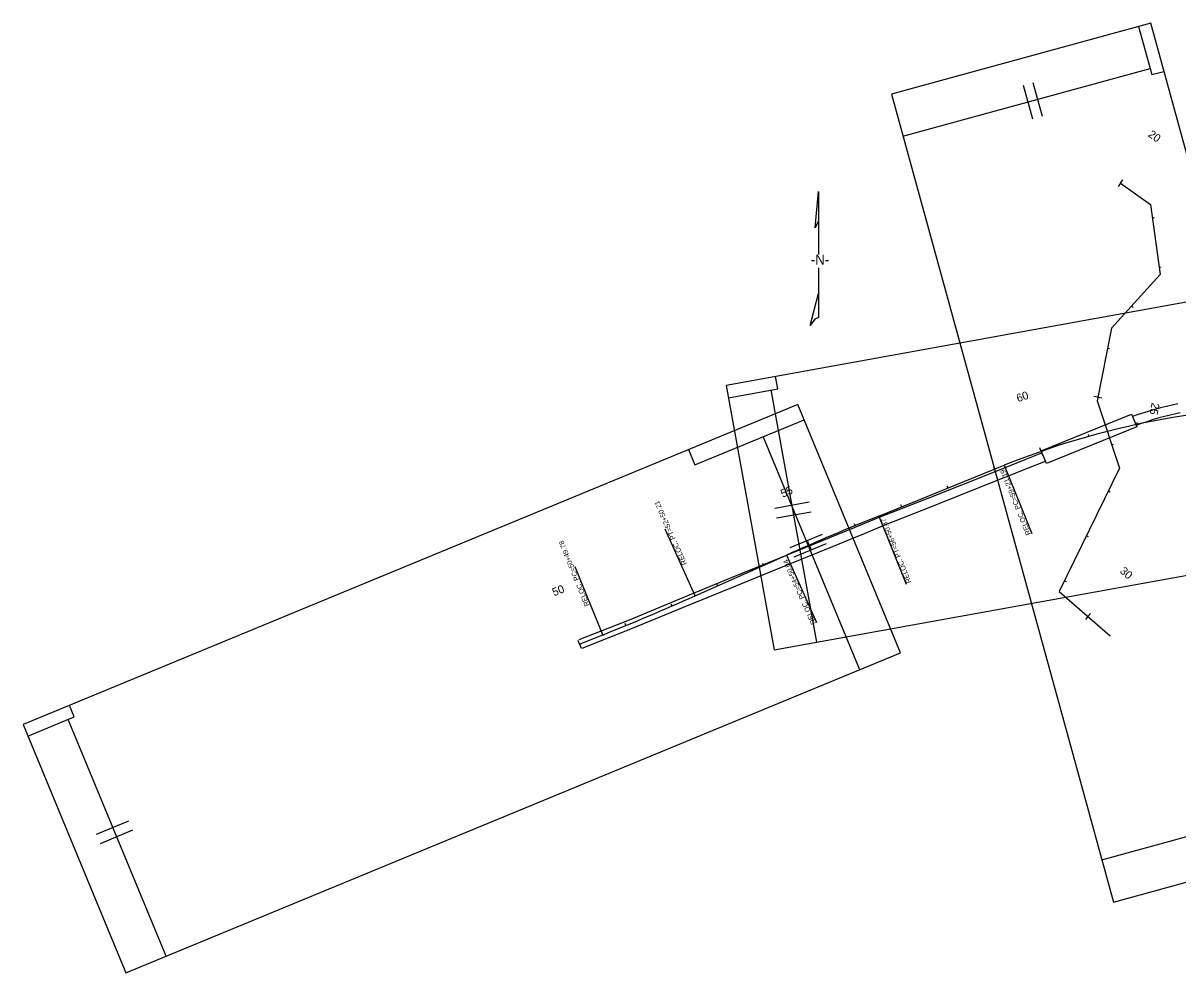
# Model space of a CAD drawing. Extents: x 1965658 to 1970277, y 1116791 to 1119319.
# Drawn here: x 1965658 to 1967966, y 1116791 to 1118690 of the extents above; entities that cross this region are included whole.
import ezdxf

# ---------------------------------------------------------------- set-up
doc = ezdxf.new("R2010")
doc.units = 0
for name, color, linetype in [('RD_EX_Bridge', 7, 'Continuous'), ('RD_EX_Misc', 7, 'Continuous'), ('RD_EX_Road', 7, 'Continuous'), ('RD_HC_CL', 7, 'Continuous'), ('RD_HC_CL_Rel', 7, 'Continuous'), ('RD_HC_Data_Rel', 7, 'Continuous'), ('RD_HC_Data_Tic', 7, 'Continuous'), ('RD_HC_Data_Tic_Rel', 7, 'Continuous'), ('RD_HC_TX_Rel_Sta50', 7, 'Continuous'), ('RD_HC_TX_Sta50', 7, 'Continuous'), ('RD_SHT_Bndy', 7, 'Continuous')]:
    doc.layers.add(name, color=color, linetype=linetype)

msp = doc.modelspace()

# ---------------------------------------------------------------- linework, layer by layer
at = {"layer": 'RD_EX_Bridge'}
msp.add_lwpolyline([(1967693.2, 1117834.7), (1967873.6, 1117908.4), (1967884, 1117883.1), (1967703.5, 1117809.4), (1967693.2, 1117834.7)], dxfattribs=at)
at = {"layer": 'RD_EX_Misc'}
for p, q in [((1967241.5, 1118281), (1967248.2, 1118353.8)), ((1967248.2, 1118353.8), (1967248.2, 1118294.5)), ((1967248.2, 1118294.5), (1967241.5, 1118281)), ((1967248.2, 1118294.5), (1967248.2, 1118253.4)), ((1967248.2, 1118253.4), (1967248.2, 1118227.2)), ((1967248.2, 1118201.1), (1967248.2, 1118149.3)), ((1967231.7, 1118085.8), (1967248.2, 1118149.3)), ((1967248.2, 1118149.3), (1967248.2, 1118141.4)), ((1967248.2, 1118141.4), (1967248.2, 1118101.8))]:
    msp.add_line(p, q, dxfattribs=at)
msp.add_lwpolyline([(1967248.2, 1118101.8), (1967241.1, 1118097.9), (1967231.7, 1118085.8)], dxfattribs=at)
at = {"layer": 'RD_EX_Road'}
msp.add_line((1967308.8, 1117656.7), (1967340, 1117669.9), dxfattribs=at)
for points in [[(1966769.5, 1117457.5), (1966870.2, 1117497.3), (1966971.2, 1117539), (1967071.1, 1117580.2), (1967172.6, 1117621.5), (1967270.8, 1117661.7), (1967321.1, 1117682.6), (1967371.5, 1117702.9), (1967470.3, 1117741.6), (1967566.7, 1117779.5), (1967661.2, 1117817.5), (1967694.6, 1117831.3)], [(1967340, 1117669.9), (1967379.3, 1117686.2), (1967476.1, 1117724.4), (1967573.9, 1117763.5), (1967667.7, 1117800.7), (1967701.6, 1117814)], [(1966775.8, 1117440.6), (1966876.2, 1117480.4), (1966978.5, 1117522.1), (1967078.3, 1117563.1), (1967180.7, 1117605.1), (1967278, 1117644.7), (1967308.8, 1117656.7)]]:
    msp.add_lwpolyline(points, dxfattribs=at)
for centre, radius, start, end in [((1968104.9, 1117261.1), 682.1, 101.7162, 109.6396), ((1968081.5, 1117359.5), 562.4, 101.3634, 110.7161)]:
    msp.add_arc(centre, radius, start, end, dxfattribs=at)
at = {"layer": 'RD_HC_CL'}
for p, q in [((1967851.7, 1118370.2), (1967911.4, 1118327.7)), ((1967911.4, 1118327.7), (1967931.1, 1118187.5)), ((1967931.1, 1118187.5), (1967834, 1118080)), ((1967834, 1118080), (1967804.8, 1117934.9)), ((1967804.8, 1117934.9), (1967849.8, 1117800.6)), ((1967849.8, 1117800.6), (1967729.3, 1117553.7)), ((1967729.3, 1117553.7), (1967830.8, 1117465.4))]:
    msp.add_line(p, q, dxfattribs=at)
at = {"layer": 'RD_HC_CL_Rel'}
for p, q in [((1967368.4, 1117704.6), (1967619.4, 1117806)), ((1967001.4, 1117545.1), (1967183.9, 1117626.3)), ((1966770.7, 1117448.1), (1966816.9, 1117466.8))]:
    msp.add_line(p, q, dxfattribs=at)
for centre, radius, start, end in [((1968232.6, 1116288.2), 1637, 87.7266, 111.9958), ((1969514.4, 1112392.1), 5729.6, 111.99584, 114.00015), ((1964670.9, 1122779.3), 5729.6, 291.9959, 294.00015)]:
    msp.add_arc(centre, radius, start, end, dxfattribs=at)
at = {"layer": 'RD_HC_Data_Rel'}
for p, q in [((1967619.4, 1117806), (1967674.6, 1117669.5)), ((1967368.4, 1117704.6), (1967423.4, 1117568.5)), ((1967001.4, 1117545.1), (1966941.9, 1117678.6)), ((1967183.9, 1117626.3), (1967243.9, 1117491.8)), ((1966816.9, 1117466.8), (1966761.8, 1117603.2))]:
    msp.add_line(p, q, dxfattribs=at)
at = {"layer": 'RD_HC_Data_Tic'}
for p, q in [((1967851.7, 1118370.2), (1967856.4, 1118376.7)), ((1967851.7, 1118370.2), (1967847.1, 1118363.7)), ((1967915.1, 1118301.2), (1967919, 1118301.7)), ((1967929, 1118202.2), (1967933, 1118202.7)), ((1967874, 1118124.2), (1967876.9, 1118121.6)), ((1967826.1, 1118040.4), (1967830, 1118039.6)), ((1967806.3, 1117942.4), (1967798.5, 1117943.9)), ((1967806.3, 1117942.4), (1967814.2, 1117940.8)), ((1967834.2, 1117847.3), (1967838, 1117848.6)), ((1967827.6, 1117755), (1967831.1, 1117753.2)), ((1967783.7, 1117665.1), (1967787.3, 1117663.4)), ((1967739.8, 1117575.2), (1967743.4, 1117573.5)), ((1967786.6, 1117503.8), (1967781.4, 1117497.8)), ((1967786.6, 1117503.8), (1967791.9, 1117509.8))]:
    msp.add_line(p, q, dxfattribs=at)
at = {"layer": 'RD_HC_Data_Tic_Rel'}
for p, q in [((1967885.6, 1117888), (1967884.7, 1117891.9)), ((1967788.6, 1117863.8), (1967787.5, 1117867.7)), ((1967693.2, 1117833.8), (1967690.6, 1117841.3)), ((1967693.2, 1117833.8), (1967695.8, 1117826.2)), ((1967599.8, 1117798.1), (1967598.3, 1117801.8)), ((1967507.1, 1117760.7), (1967505.6, 1117764.4)), ((1967414.4, 1117723.2), (1967412.9, 1117726.9)), ((1967321.7, 1117685.5), (1967320.2, 1117689.2)), ((1967229.7, 1117646.5), (1967226.5, 1117653.8)), ((1967229.7, 1117646.5), (1967232.9, 1117639.1)), ((1967138.2, 1117606), (1967136.6, 1117609.6)), ((1967046.9, 1117565.3), (1967045.2, 1117569)), ((1966955.4, 1117524.8), (1966953.8, 1117528.5)), ((1966863.4, 1117485.8), (1966861.8, 1117489.5)), ((1966770.7, 1117448.1), (1966767.7, 1117455.5)), ((1966770.7, 1117448.1), (1966773.7, 1117440.7))]:
    msp.add_line(p, q, dxfattribs=at)
at = {"layer": 'RD_SHT_Bndy'}
for p, q in [((1967416.8, 1118463.9), (1967911, 1118599.7)), ((1967657, 1118566.2), (1967675.6, 1118498.7)), ((1967676.3, 1118571.5), (1967694.9, 1118504)), ((1967245, 1117452.4), (1967153.8, 1117956.7)), ((1967330.5, 1117397.3), (1967137.8, 1117863.4)), ((1967161, 1117720.5), (1967229.8, 1117732.9)), ((1967164.5, 1117700.8), (1967233.4, 1117713.2)), ((1967191.6, 1117641.6), (1967256.3, 1117668.3)), ((1967199.3, 1117623.1), (1967264, 1117649.8)), ((1965944.2, 1116824.4), (1965748.4, 1117298)), ((1967814.2, 1117017.5), (1968300.5, 1117151.1)), ((1965805.4, 1117068.6), (1965870.1, 1117095.4)), ((1965813, 1117050.1), (1965877.7, 1117076.9))]:
    msp.add_line(p, q, dxfattribs=at)
for points in [[(1967393.8, 1118547.8), (1967837.6, 1116932.6), (1968355.8, 1117075.1), (1967912, 1118690.2)], [(1967159.4, 1117436.9), (1968807.6, 1117735.1), (1968712, 1118264), (1967063.7, 1117965.8)], [(1965863.8, 1116791.1), (1967411.8, 1117430.9), (1967206.5, 1117927.7), (1965658.5, 1117287.9)]]:
    msp.add_lwpolyline(points, close=True, dxfattribs=at)
for points in [[(1967887.9, 1118683.5), (1967914.4, 1118587.1), (1967938.5, 1118593.7)], [(1967068.2, 1117941.2), (1967166.6, 1117959), (1967162.2, 1117983.6)], [(1966988.5, 1117837.6), (1967001.2, 1117806.9), (1967219.2, 1117897)], [(1965668.1, 1117264.8), (1965760.5, 1117303), (1965750.9, 1117326.1)]]:
    msp.add_lwpolyline(points, dxfattribs=at)

# ---------------------------------------------------------------- texts
at = {"layer": 'RD_EX_Misc'}
msp.add_text('-N-', height=20, dxfattribs=at).set_placement((1967232.6, 1118207.4))
at = {"layer": 'RD_HC_Data_Rel'}
for s, rotation, p in [('RELOC. PC=59+21.19', 111.9958, (1967672.7, 1117668.7)), ('RELOC. PT=52+50.21', 114.0002, (1966985.2, 1117609.3)), ('RELOC. PT=56+50.47', 111.9958, (1967433.8, 1117572.5)), ('RELOC. PC=50+49.78', 111.9959, (1966790.7, 1117526.3)), ('RELOC. PC=54+50.04', 114.0002, (1967243.1, 1117490.4))]:
    msp.add_text(s, height=10, rotation=rotation, dxfattribs=at).set_placement(p)
at = {"layer": 'RD_HC_TX_Rel_Sta50'}
for s, rotation, p in [('60', 19.2374, (1967647, 1117932)), ('55', 23.5006, (1967176.6, 1117741.1)), ('50', 21.9959, (1966719.8, 1117544))]:
    msp.add_text(s, height=16, rotation=rotation, dxfattribs=at).set_placement(p)
at = {"layer": 'RD_HC_TX_Sta50'}
for s, rotation, p in [('20', 324.4755, (1967905.5, 1118464.6)), ('25', 258.6104, (1967914.4, 1117932.1)), ('30', 318.9993, (1967849.1, 1117592.6))]:
    msp.add_text(s, height=16, rotation=rotation, dxfattribs=at).set_placement(p)

doc.saveas('drawing.dxf')
